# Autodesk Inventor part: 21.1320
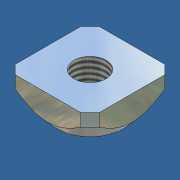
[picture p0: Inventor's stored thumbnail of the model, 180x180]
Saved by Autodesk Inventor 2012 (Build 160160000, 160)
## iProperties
Created: 2006-12
Part Number: 21.1320
Document SubType Name: Modeling
Designer: Andy Moles
Material: Steel, Mild
Density: 7.86 g/cm^3
Mass: 5.31619 g
Surface Area: 5.644 cm^2
Volume: 0.67636 cm^3
Description: M5 SQUARE NUT
Vendor: S
Author: Andy Moles
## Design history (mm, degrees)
sketch "Sketch2"
  geometry: L1 (-5.086, -6.5)-(5.086, -6.5); L2 (6.5, -5.086)-(6.5, 5.086); L3 (5.086, 6.5)-(-5.086, 6.5); L4 (-6.5, 5.086)-(-6.5, -5.086); L5 (-6.5, 6.5)-(6.5, -6.5); L6 (5.086, 6.5)-(6.5, 5.086); L7 (0, -6.5)-(0, 6.5); L8 (-6.5, 0)-(6.5, 0); L9 (-5.086, 6.5)-(-6.5, 5.086); L10 (-5.086, -6.5)-(-6.5, -5.086); L11 (5.086, -6.5)-(6.5, -5.086); C1 r 2.5 at (0, 0); 2 further points
  constraints: 22 end point, 6 symmetric about line, 4 parallel, 3 midpoint, 2 coincident, 2 perpendicular, 1 centre point, 1 horizontal
  dimensions: "THREAD" = 5 diameter of C1; "d3" = 45 deg angle of L3 L6 (derived); "d4" = 2 distance of L3.start L2.end
extrude "Extrusion1" new body sketch "Sketch2" distance "d5" = 5.5; taper "d6" = 0 deg
workplane "Work Plane1"
sketch "Sketch4"
  geometry: L1 (10.692, 0)-(5.692, 0) reference; L2 (8.192, 0)-(13.192, 0); L3 (16.385, 5.5)-(16.385, 3.5); L4 (13.192, 0)-(16.797, 3.952); L5 (13.192, 0)-(16.385, 0); L6 (16.385, 3.5)-(16.385, 0); L7 (16.797, 3.952)-(16.797, -0.412); L8 (16.797, -0.412)-(13.192, -0.412); L9 (13.192, -0.412)-(13.192, 0); L10 (8.192, 5.5)-(8.192, 0); L11 (16.385, 5.5)-(16.385, 0) reference; L12 (16.385, 3.5)-(17.502, 3.5); L13 (9.192, 5.5)-(16.385, 5.5) reference
  constraints: 20 end point, 6 perpendicular, 1 collinear, 1 midpoint, 1 parallel, 1 point on line
  dimensions: "d10" = 5 distance of L2.start L2.end; "d15" = 2 distance between parallel lines of L12 L13
revolve "Revolution1" sketch "Sketch4" stored, may be unused: angle "d12" = 90 deg
thread "Thread1" dims "d13" = 10, "d14" = 0
body "Solid1"
